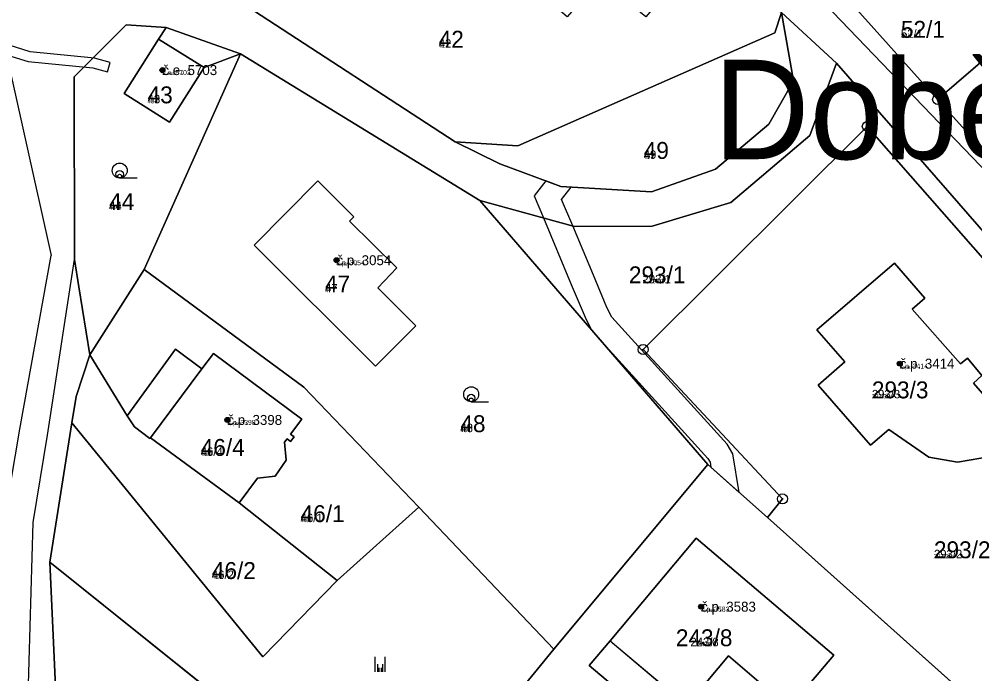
# Model space of a CAD drawing. Extents: x -759873 to -758487, y -975024 to -973516.
# Drawn here: x -759190.5 to -759094.4, y -974362.2 to -974296.3 of the extents above; entities that cross this region are included whole.
import ezdxf

# ---------------------------------------------------------------- set-up
doc = ezdxf.new("R2010")
doc.units = 0
for name, color, linetype in [('KAT_02_hranice parcel', 7, 'Continuous'), ('KAT_03_1000_st čísla parcelní', 7, 'Continuous'), ('KAT_03_1000_čísla parcelní', 7, 'Continuous'), ('KAT_03_1000_čísla popisná', 7, 'Continuous'), ('KAT_03_250_st čísla parcelní', 7, 'Continuous'), ('KAT_03_250_čísla parcelní', 7, 'Continuous'), ('KAT_03_250_čísla popisná', 7, 'Continuous'), ('KAT_03_500_st čísla parcelní', 7, 'Continuous'), ('KAT_03_500_čísla parcelní', 7, 'Continuous'), ('KAT_03_500_čísla popisná', 7, 'Continuous'), ('KAT_04_vnitřní kresba', 7, 'Continuous'), ('KAT_05_1000_značky kultur', 7, 'Continuous'), ('KAT_05_250_značky kultur', 7, 'Continuous'), ('KAT_05_500_značky kultur', 7, 'Continuous'), ('KAT_07_1000_značky budov', 7, 'Continuous'), ('KAT_07_250_značky budov', 7, 'Continuous'), ('KAT_07_500_značky budov', 7, 'Continuous'), ('KAT_10_věcná břemena', 7, 'Continuous'), ('KAT_11_značky bodu BP', 7, 'Continuous'), ('KAT_13_popis', 7, 'Continuous'), ('KAT_14_plocha_budovy', 7, 'Continuous'), ('KAT_14_plocha_pozemek', 7, 'Continuous')]:
    doc.layers.add(name, color=color, linetype=linetype)

msp = doc.modelspace()

# ---------------------------------------------------------------- linework, layer by layer
at = {"layer": 'KAT_02_hranice parcel'}
for p, q in [((-759166.96, -974295.46), (-759146.69, -974308.69)), ((-759108.36, -974300.77), (-759113.88, -974295.69)), ((-759168.24, -974299.85), (-759175.74, -974297.18)), ((-759098.18, -974304.42), (-759091.02, -974298.25)), ((-759177.94, -974321.52), (-759168.24, -974299.85)), ((-759144.18, -974314.59), (-759168.24, -974299.85)), ((-759090.1, -974313.42), (-759098.18, -974304.42)), ((-759121.28, -974341.12), (-759144.18, -974314.59)), ((-759183.41, -974330.1), (-759177.94, -974321.52)), ((-759183.41, -974330.1), (-759179.65, -974336.24)), ((-759185.19, -974336.95), (-759187.42, -974350.96)), ((-759136.75, -974359.69), (-759121.28, -974341.12)), ((-759115.29, -974346.47), (-759121.28, -974341.12)), ((-759168.4, -974345), (-759158.52, -974352.8)), ((-759150.34, -974345.43), (-759158.52, -974352.8)), ((-759136.75, -974359.69), (-759150.34, -974345.43)), ((-759090.51, -974368.61), (-759115.29, -974346.47)), ((-759187.42, -974350.96), (-759165.67, -974368.38)), ((-759152.45, -974378.9), (-759136.75, -974359.69))]:
    msp.add_line(p, q, dxfattribs=at)
for points in [[(-759109.41, -974292.79), (-759106.6, -974295.05), (-759098.18, -974304.42)], [(-759146.69, -974308.69), (-759142.19, -974310.89), (-759136.07, -974313.18), (-759126.94, -974313.7), (-759120.52, -974311.43), (-759115.16, -974306.92), (-759112.66, -974302.54), (-759113.88, -974295.69)], [(-759146.69, -974308.69), (-759140.38, -974309.09), (-759114.55, -974297.73), (-759113.88, -974295.69)], [(-759175.74, -974297.18), (-759179.76, -974296.91), (-759184.97, -974302.14), (-759184.94, -974320.52), (-759184.5, -974323.28), (-759183.41, -974330.1)], [(-759175.74, -974297.18), (-759176.5, -974298.37), (-759179.95, -974303.82), (-759175.4, -974306.71), (-759171.92, -974301.2), (-759168.24, -974299.85)], [(-759144.18, -974314.59), (-759134.68, -974317.19), (-759126.87, -974317.18), (-759118.98, -974314.8), (-759111.04, -974308.04), (-759108.36, -974300.77)], [(-759108.36, -974300.77), (-759091.71, -974319.84), (-759079.48, -974333.82)], [(-759115.29, -974346.47), (-759113.77, -974344.59), (-759127.78, -974329.56), (-759105.25, -974307.13), (-759087.1, -974327.84)], [(-759160.47, -974312.62), (-759166.89, -974319.07), (-759154.67, -974331.25), (-759150.63, -974327.18), (-759154.45, -974323.35), (-759152.55, -974321.36), (-759157.28, -974316.65), (-759156.85, -974316.22), (-759160.47, -974312.62)], [(-759150.34, -974345.43), (-759161.87, -974333.34), (-759177.94, -974321.52)], [(-759104.94, -974339.2), (-759110.18, -974333.15), (-759107.52, -974330.8), (-759110.32, -974327.6), (-759102.52, -974320.9), (-759099.46, -974324.4), (-759100.75, -974325.51), (-759095.89, -974331.01), (-759095.18, -974330.45), (-759093.72, -974332.19), (-759094.58, -974332.95), (-759089.76, -974338.48), (-759092.68, -974340.31), (-759096.19, -974340.9), (-759099.06, -974340.38), (-759103.1, -974337.6), (-759104.94, -974339.2)], [(-759183.41, -974330.1), (-759184.77, -974334.29), (-759185.19, -974336.95)], [(-759179.65, -974336.24), (-759174.8, -974329.55), (-759172.14, -974331.52), (-759170.98, -974329.97), (-759162.08, -974336.56), (-759163.21, -974338.08), (-759162.86, -974338.34), (-759163.21, -974338.82), (-759163.57, -974338.56), (-759163.84, -974338.89), (-759163.66, -974340.69), (-759164.76, -974342.3), (-759166.54, -974342.52), (-759168.4, -974345)], [(-759158.52, -974352.8), (-759166, -974360.47), (-759185.19, -974336.95)], [(-759168.4, -974345), (-759177.3, -974338.44), (-759177.37, -974338.51), (-759178.91, -974337.34), (-759179.65, -974336.24)], [(-759121.24, -974365.32), (-759122.11, -974366.39), (-759121.96, -974366.53), (-759124.06, -974369.05), (-759133.19, -974361.34), (-759131.11, -974358.85), (-759122.46, -974348.54), (-759108.61, -974360.31), (-759113.09, -974365.59), (-759119.2, -974360.38), (-759122.47, -974364.3), (-759121.24, -974365.32)], [(-759185.4, -974377.64), (-759186.3, -974375.24), (-759187.42, -974350.96)]]:
    msp.add_lwpolyline(points, dxfattribs=at)
at = {"layer": 'KAT_03_1000_čísla popisná'}
for centre in [(-759176.1, -974301.47), (-759158.6, -974320.59), (-759101.99, -974330.99), (-759169.57, -974336.65), (-759121.95, -974355.43)]:
    msp.add_circle(centre, 0.25, dxfattribs=at)
at = {"layer": 'KAT_03_250_čísla popisná'}
for centre in [(-759176.1, -974301.47), (-759158.6, -974320.59), (-759101.99, -974330.99), (-759169.57, -974336.65), (-759121.95, -974355.43)]:
    msp.add_circle(centre, 0.0625, dxfattribs=at)
at = {"layer": 'KAT_03_500_čísla popisná'}
for centre in [(-759176.1, -974301.47), (-759158.6, -974320.59), (-759101.99, -974330.99), (-759169.57, -974336.65), (-759121.95, -974355.43)]:
    msp.add_circle(centre, 0.125, dxfattribs=at)
at = {"layer": 'KAT_04_vnitřní kresba'}
for p, q in [((-759109.56, -974294.77), (-759088.49, -974316.71)), ((-759192.55, -974296.61), (-759187.28, -974320.12)), ((-759176.5, -974298.37), (-759171.92, -974301.2)), ((-759190.42, -974337.58), (-759187.28, -974320.12)), ((-759187.65, -974338.19), (-759184.94, -974320.52)), ((-759177.3, -974338.44), (-759172.14, -974331.52)), ((-759191.86, -974346.12), (-759190.42, -974337.58)), ((-759189.09, -974346.96), (-759187.65, -974338.19)), ((-759189.76, -974370.74), (-759189.09, -974346.96)), ((-759131.11, -974358.85), (-759123.37, -974365.38))]:
    msp.add_line(p, q, dxfattribs=at)
at = {"layer": 'KAT_05_1000_značky kultur'}
for p, q in [((-759180.393, -974312.32), (-759178.643, -974312.32)), ((-759145.063, -974334.82), (-759143.313, -974334.82)), ((-759154.711, -974361.97), (-759154.711, -974360.47)), ((-759153.71, -974361.97), (-759153.71, -974360.47))]:
    msp.add_line(p, q, dxfattribs=at)
for centre in [(-759180.393, -974311.57), (-759145.063, -974334.07)]:
    msp.add_circle(centre, 0.75, dxfattribs=at)
at = {"layer": 'KAT_05_250_značky kultur'}
for p, q in [((-759180.398, -974312.32), (-759179.961, -974312.32)), ((-759145.068, -974334.82), (-759144.631, -974334.82)), ((-759154.328, -974361.97), (-759154.328, -974361.595)), ((-759154.078, -974361.97), (-759154.078, -974361.595))]:
    msp.add_line(p, q, dxfattribs=at)
for centre in [(-759180.398, -974312.132), (-759145.068, -974334.632)]:
    msp.add_circle(centre, 0.187, dxfattribs=at)
at = {"layer": 'KAT_05_500_značky kultur'}
for p, q in [((-759180.397, -974312.32), (-759179.522, -974312.32)), ((-759145.067, -974334.82), (-759144.192, -974334.82)), ((-759154.456, -974361.97), (-759154.456, -974361.22)), ((-759153.955, -974361.97), (-759153.955, -974361.22))]:
    msp.add_line(p, q, dxfattribs=at)
for centre in [(-759180.396, -974311.945), (-759145.066, -974334.445)]:
    msp.add_circle(centre, 0.375, dxfattribs=at)
at = {"layer": 'KAT_07_1000_značky budov'}
for centre in [(-759176.107, -974301.469), (-759158.607, -974320.589), (-759101.997, -974330.989), (-759169.577, -974336.649), (-759121.957, -974355.429)]:
    msp.add_circle(centre, 0.175, dxfattribs=at)
at = {"layer": 'KAT_07_250_značky budov'}
for centre in [(-759176.102, -974301.47), (-759158.602, -974320.59), (-759101.992, -974330.99), (-759169.572, -974336.65), (-759121.952, -974355.43)]:
    msp.add_circle(centre, 0.0437, dxfattribs=at)
at = {"layer": 'KAT_07_500_značky budov'}
for centre in [(-759176.103, -974301.47), (-759158.603, -974320.59), (-759101.993, -974330.99), (-759169.573, -974336.65), (-759121.953, -974355.43)]:
    msp.add_circle(centre, 0.0875, dxfattribs=at)
at = {"layer": 'KAT_10_věcná břemena'}
for points in [[(-759192.25, -974298.73), (-759192.1, -974299.83), (-759189.6, -974300.61), (-759183.11, -974301.25), (-759181.62, -974301.65), (-759181.36, -974300.69), (-759182.93, -974300.27), (-759189.4, -974299.63)], [(-759119.34, -974339.09), (-759130.92, -974326.32), (-759131.43, -974325.33), (-759132.78, -974322.1), (-759134.86, -974317.14), (-759135.97, -974314.49), (-759135, -974313.24), (-759136.07, -974313.18), (-759137.56, -974312.62), (-759138.73, -974314.13), (-759137.8, -974316.33), (-759135, -974323.02), (-759133.61, -974326.33), (-759132.99, -974327.55), (-759131.87, -974328.85), (-759121.28, -974340.53), (-759121.06, -974340.89), (-759120.97, -974341.39), (-759118.12, -974343.94), (-759118.76, -974340.05)]]:
    msp.add_lwpolyline(points, close=True, dxfattribs=at)
at = {"layer": 'KAT_11_značky bodu BP'}
for centre, radius in [((-759098.18, -974304.42), 0.5), ((-759098.18, -974304.42), 0.0303), ((-759105.25, -974307.13), 0.5), ((-759105.25, -974307.13), 0.0303), ((-759127.78, -974329.56), 0.5), ((-759127.78, -974329.56), 0.0303), ((-759113.77, -974344.59), 0.5), ((-759113.77, -974344.59), 0.0303)]:
    msp.add_circle(centre, radius, dxfattribs=at)
at = {"layer": 'KAT_14_plocha_budovy'}
for points in [[(-759176.5, -974298.37), (-759179.95, -974303.82), (-759175.4, -974306.71), (-759171.92, -974301.2)], [(-759157.28, -974316.65), (-759156.85, -974316.22), (-759160.47, -974312.62), (-759166.89, -974319.07), (-759154.67, -974331.25), (-759150.63, -974327.18), (-759154.45, -974323.35), (-759152.55, -974321.36)], [(-759110.18, -974333.15), (-759104.94, -974339.2), (-759103.1, -974337.6), (-759099.06, -974340.38), (-759096.19, -974340.9), (-759092.68, -974340.31), (-759089.76, -974338.48), (-759094.58, -974332.95), (-759093.72, -974332.19), (-759095.18, -974330.45), (-759095.89, -974331.01), (-759100.75, -974325.51), (-759099.46, -974324.4), (-759102.52, -974320.9), (-759110.32, -974327.6), (-759107.52, -974330.8)], [(-759163.84, -974338.89), (-759163.57, -974338.56), (-759163.21, -974338.82), (-759162.86, -974338.34), (-759163.21, -974338.08), (-759162.08, -974336.56), (-759170.98, -974329.97), (-759172.14, -974331.52), (-759177.3, -974338.44), (-759168.4, -974345), (-759166.54, -974342.52), (-759164.76, -974342.3), (-759163.66, -974340.69)], [(-759131.11, -974358.85), (-759123.37, -974365.38), (-759122.47, -974364.3), (-759119.2, -974360.38), (-759113.09, -974365.59), (-759108.61, -974360.31), (-759122.46, -974348.54)]]:
    msp.add_lwpolyline(points, close=True, dxfattribs=at)
at = {"layer": 'KAT_14_plocha_pozemek'}
for points in [[(-759090.1, -974313.42), (-759098.18, -974304.42), (-759106.6, -974295.05), (-759109.41, -974292.79), (-759130.63, -974274.73), (-759134.45, -974270.58), (-759142.01, -974265.12), (-759153.59, -974259.47), (-759166.35, -974257.52), (-759171.99, -974258.88), (-759190.18, -974262.03), (-759212.16, -974265.84)], [(-759228.43, -974270.82), (-759182.46, -974265.89), (-759176.65, -974264.97), (-759164.95, -974263.13), (-759162.53, -974263.23), (-759159.62, -974263.35), (-759148.86, -974268.28), (-759137.55, -974276.08), (-759137.41, -974276.19), (-759133.42, -974279.5), (-759126.27, -974285.42), (-759121.65, -974289.25), (-759113.88, -974295.69), (-759108.36, -974300.77), (-759091.71, -974319.84), (-759079.48, -974333.82), (-759074.99, -974338.96), (-759070.5, -974344.1), (-759060.98, -974351.22), (-759051.14, -974355.72), (-759039.97, -974358.1), (-759037.67, -974358.59), (-759031.63, -974358.94), (-758978.01, -974362.06)], [(-759186.3, -974375.24), (-759187.42, -974350.96), (-759185.19, -974336.95), (-759184.77, -974334.29), (-759183.41, -974330.1), (-759184.5, -974323.28), (-759184.94, -974320.52), (-759184.97, -974302.14), (-759179.76, -974296.91), (-759175.74, -974297.18), (-759168.24, -974299.85), (-759144.18, -974314.59), (-759134.68, -974317.19), (-759126.87, -974317.18), (-759118.98, -974314.8), (-759111.04, -974308.04), (-759108.36, -974300.77), (-759113.88, -974295.69), (-759112.66, -974302.54), (-759115.16, -974306.92), (-759120.52, -974311.43), (-759126.94, -974313.7), (-759136.07, -974313.18), (-759142.19, -974310.89), (-759146.69, -974308.69), (-759166.96, -974295.46)]]:
    msp.add_lwpolyline(points, dxfattribs=at)
for points in [[(-759146.69, -974308.69), (-759140.38, -974309.09), (-759114.55, -974297.73), (-759113.88, -974295.69), (-759121.65, -974289.25), (-759127.52, -974296.12), (-759132.15, -974292.31), (-759135.42, -974296.13), (-759140.96, -974291.39), (-759139.65, -974289.86), (-759144.55, -974286.05), (-759142.65, -974283.61), (-759143.3, -974283.11), (-759153.27, -974280.7), (-759166.96, -974295.46)], [(-759098.18, -974304.42), (-759091.02, -974298.25), (-759100.58, -974286.17), (-759109.41, -974292.79), (-759106.6, -974295.05)], [(-759112.66, -974302.54), (-759113.88, -974295.69), (-759114.55, -974297.73), (-759140.38, -974309.09), (-759146.69, -974308.69), (-759142.19, -974310.89), (-759136.07, -974313.18), (-759126.94, -974313.7), (-759120.52, -974311.43), (-759115.16, -974306.92)], [(-759168.24, -974299.85), (-759171.92, -974301.2), (-759175.4, -974306.71), (-759179.95, -974303.82), (-759176.5, -974298.37), (-759175.74, -974297.18), (-759179.76, -974296.91), (-759184.97, -974302.14), (-759184.94, -974320.52), (-759184.5, -974323.28), (-759183.41, -974330.1), (-759177.94, -974321.52)], [(-759175.4, -974306.71), (-759171.92, -974301.2), (-759168.24, -974299.85), (-759175.74, -974297.18), (-759176.5, -974298.37), (-759179.95, -974303.82)], [(-759091.02, -974298.25), (-759098.18, -974304.42), (-759090.1, -974313.42), (-759083.84, -974307.33)], [(-759121.28, -974341.12), (-759144.18, -974314.59), (-759168.24, -974299.85), (-759177.94, -974321.52), (-759161.87, -974333.34), (-759150.34, -974345.43), (-759136.75, -974359.69)], [(-759087.1, -974327.84), (-759079.47, -974336.54), (-759079.48, -974333.82), (-759091.71, -974319.84), (-759108.36, -974300.77), (-759111.04, -974308.04), (-759118.98, -974314.8), (-759126.87, -974317.18), (-759134.68, -974317.19), (-759144.18, -974314.59), (-759121.28, -974341.12), (-759115.29, -974346.47), (-759113.77, -974344.59), (-759127.78, -974329.56), (-759105.25, -974307.13)], [(-759087.1, -974327.84), (-759105.25, -974307.13), (-759127.78, -974329.56), (-759113.77, -974344.59), (-759115.29, -974346.47), (-759090.51, -974368.61), (-759075.8, -974349.7), (-759079.45, -974344.13)], [(-759160.47, -974312.62), (-759166.89, -974319.07), (-759154.67, -974331.25), (-759150.63, -974327.18), (-759154.45, -974323.35), (-759152.55, -974321.36), (-759157.28, -974316.65), (-759156.85, -974316.22)], [(-759160.47, -974312.62), (-759156.85, -974316.22), (-759157.28, -974316.65), (-759152.55, -974321.36), (-759154.45, -974323.35), (-759150.63, -974327.18), (-759154.67, -974331.25), (-759166.89, -974319.07)], [(-759161.87, -974333.34), (-759177.94, -974321.52), (-759183.41, -974330.1), (-759179.65, -974336.24), (-759174.8, -974329.55), (-759172.14, -974331.52), (-759170.98, -974329.97), (-759162.08, -974336.56), (-759163.21, -974338.08), (-759162.86, -974338.34), (-759163.21, -974338.82), (-759163.57, -974338.56), (-759163.84, -974338.89), (-759163.66, -974340.69), (-759164.76, -974342.3), (-759166.54, -974342.52), (-759168.4, -974345), (-759158.52, -974352.8), (-759150.34, -974345.43)], [(-759104.94, -974339.2), (-759103.1, -974337.6), (-759099.06, -974340.38), (-759096.19, -974340.9), (-759092.68, -974340.31), (-759089.76, -974338.48), (-759094.58, -974332.95), (-759093.72, -974332.19), (-759095.18, -974330.45), (-759095.89, -974331.01), (-759100.75, -974325.51), (-759099.46, -974324.4), (-759102.52, -974320.9), (-759110.32, -974327.6), (-759107.52, -974330.8), (-759110.18, -974333.15)], [(-759104.94, -974339.2), (-759110.18, -974333.15), (-759107.52, -974330.8), (-759110.32, -974327.6), (-759102.52, -974320.9), (-759099.46, -974324.4), (-759100.75, -974325.51), (-759095.89, -974331.01), (-759095.18, -974330.45), (-759093.72, -974332.19), (-759094.58, -974332.95), (-759089.76, -974338.48), (-759092.68, -974340.31), (-759096.19, -974340.9), (-759099.06, -974340.38), (-759103.1, -974337.6)], [(-759183.41, -974330.1), (-759184.77, -974334.29), (-759185.19, -974336.95), (-759166, -974360.47), (-759158.52, -974352.8), (-759168.4, -974345), (-759177.3, -974338.44), (-759177.37, -974338.51), (-759178.91, -974337.34), (-759179.65, -974336.24)], [(-759179.65, -974336.24), (-759178.91, -974337.34), (-759177.37, -974338.51), (-759177.3, -974338.44), (-759168.4, -974345), (-759166.54, -974342.52), (-759164.76, -974342.3), (-759163.66, -974340.69), (-759163.84, -974338.89), (-759163.57, -974338.56), (-759163.21, -974338.82), (-759162.86, -974338.34), (-759163.21, -974338.08), (-759162.08, -974336.56), (-759170.98, -974329.97), (-759172.14, -974331.52), (-759174.8, -974329.55)], [(-759136.75, -974359.69), (-759150.34, -974345.43), (-759158.52, -974352.8), (-759166, -974360.47), (-759185.19, -974336.95), (-759187.42, -974350.96), (-759165.67, -974368.38), (-759152.45, -974378.9)], [(-759090.51, -974368.61), (-759115.29, -974346.47), (-759121.28, -974341.12), (-759136.75, -974359.69), (-759152.45, -974378.9), (-759132.98, -974393.31), (-759125.43, -974399.29), (-759101.95, -974417.87), (-759100.34, -974415.37), (-759089.09, -974397.95), (-759086.82, -974394.42), (-759097.98, -974384.46), (-759087.85, -974371.54), (-759087.6, -974371.21)], [(-759121.24, -974365.32), (-759122.11, -974366.39), (-759121.96, -974366.53), (-759124.06, -974369.05), (-759133.19, -974361.34), (-759131.11, -974358.85), (-759122.46, -974348.54), (-759108.61, -974360.31), (-759113.09, -974365.59), (-759119.2, -974360.38), (-759122.47, -974364.3)], [(-759121.24, -974365.32), (-759122.47, -974364.3), (-759119.2, -974360.38), (-759113.09, -974365.59), (-759108.61, -974360.31), (-759122.46, -974348.54), (-759131.11, -974358.85), (-759133.19, -974361.34), (-759124.06, -974369.05), (-759121.96, -974366.53), (-759122.11, -974366.39)], [(-759180.91, -974370.79), (-759177.89, -974367.29), (-759176.03, -974365.12), (-759174.73, -974365.06), (-759167.44, -974371.17), (-759165.67, -974368.38), (-759187.42, -974350.96), (-759186.3, -974375.24), (-759185.4, -974377.64), (-759176.25, -974385.03), (-759173.96, -974381.43), (-759176.57, -974379.26), (-759178.39, -974377.73), (-759182.6, -974374.24), (-759182.71, -974372.92)]]:
    msp.add_lwpolyline(points, close=True, dxfattribs=at)

# ---------------------------------------------------------------- texts
at = {"layer": 'KAT_03_1000_st čísla parcelní'}
for s, p in [('43', (-759177.59, -974304.809)), ('47', (-759159.76, -974323.83)), ('293/3', (-759104.79, -974334.48)), ('46/4', (-759172.25, -974340.27)), ('243/8', (-759124.493, -974359.41))]:
    msp.add_text(s, height=1.7, dxfattribs=at).set_placement(p)
at = {"layer": 'KAT_03_1000_čísla parcelní'}
for s, p in [('52/1', (-759101.87, -974298.22)), ('42', (-759148.33, -974299.22)), ('49', (-759127.72, -974310.4)), ('44', (-759181.45, -974315.549)), ('293/1', (-759129.213, -974322.91)), ('48', (-759146.15, -974337.88)), ('46/1', (-759162.21, -974346.929)), ('293/2', (-759098.55, -974350.559)), ('46/2', (-759171.13, -974352.65))]:
    msp.add_text(s, height=1.7, dxfattribs=at).set_placement(p)
at = {"layer": 'KAT_03_1000_čísla popisná'}
for s, p in [('č.e. 5703', (-759176.1, -974301.97)), ('č.p. 3054', (-759158.6, -974321.09)), ('č.p. 3414', (-759101.99, -974331.49)), ('č.p. 3398', (-759169.57, -974337.15)), ('č.p. 3583', (-759121.95, -974355.93))]:
    msp.add_text(s, height=1, dxfattribs=at).set_placement(p)
at = {"layer": 'KAT_03_250_st čísla parcelní'}
for s, p in [('43', (-759177.59, -974304.809)), ('47', (-759159.76, -974323.83)), ('293/3', (-759104.79, -974334.48)), ('46/4', (-759172.25, -974340.27)), ('243/8', (-759122.305, -974359.41))]:
    msp.add_text(s, height=0.425, dxfattribs=at).set_placement(p)
at = {"layer": 'KAT_03_250_čísla parcelní'}
for s, p in [('52/1', (-759101.87, -974298.22)), ('42', (-759148.33, -974299.22)), ('49', (-759127.72, -974310.4)), ('44', (-759181.45, -974315.549)), ('293/1', (-759127.149, -974322.91)), ('48', (-759146.15, -974337.88)), ('46/1', (-759162.21, -974346.929)), ('293/2', (-759098.55, -974350.559)), ('46/2', (-759171.13, -974352.65))]:
    msp.add_text(s, height=0.425, dxfattribs=at).set_placement(p)
at = {"layer": 'KAT_03_250_čísla popisná'}
for s, p in [('č.e. 5703', (-759176.1, -974301.97)), ('č.p. 3054', (-759158.6, -974321.09)), ('č.p. 3414', (-759101.99, -974331.49)), ('č.p. 3398', (-759169.57, -974337.15)), ('č.p. 3583', (-759121.95, -974355.93))]:
    msp.add_text(s, height=0.25, dxfattribs=at).set_placement(p)
at = {"layer": 'KAT_03_500_st čísla parcelní'}
for s, p in [('43', (-759177.59, -974304.809)), ('47', (-759159.76, -974323.83)), ('293/3', (-759104.79, -974334.48)), ('46/4', (-759172.25, -974340.27)), ('243/8', (-759123.034, -974359.41))]:
    msp.add_text(s, height=0.85, dxfattribs=at).set_placement(p)
at = {"layer": 'KAT_03_500_čísla parcelní'}
for s, p in [('52/1', (-759101.87, -974298.22)), ('42', (-759148.33, -974299.22)), ('49', (-759127.72, -974310.4)), ('44', (-759181.45, -974315.549)), ('293/1', (-759127.837, -974322.91)), ('48', (-759146.15, -974337.88)), ('46/1', (-759162.21, -974346.929)), ('293/2', (-759098.55, -974350.559)), ('46/2', (-759171.13, -974352.65))]:
    msp.add_text(s, height=0.85, dxfattribs=at).set_placement(p)
at = {"layer": 'KAT_03_500_čísla popisná'}
for s, p in [('č.e. 5703', (-759176.1, -974301.97)), ('č.p. 3054', (-759158.6, -974321.09)), ('č.p. 3414', (-759101.99, -974331.49)), ('č.p. 3398', (-759169.57, -974337.15)), ('č.p. 3583', (-759121.95, -974355.93))]:
    msp.add_text(s, height=0.5, dxfattribs=at).set_placement(p)
at = {"layer": 'KAT_13_popis'}
msp.add_text('Dobětice 757772', height=10, dxfattribs=at).set_placement((-759120.712, -974310.427))

doc.saveas('drawing.dxf')
